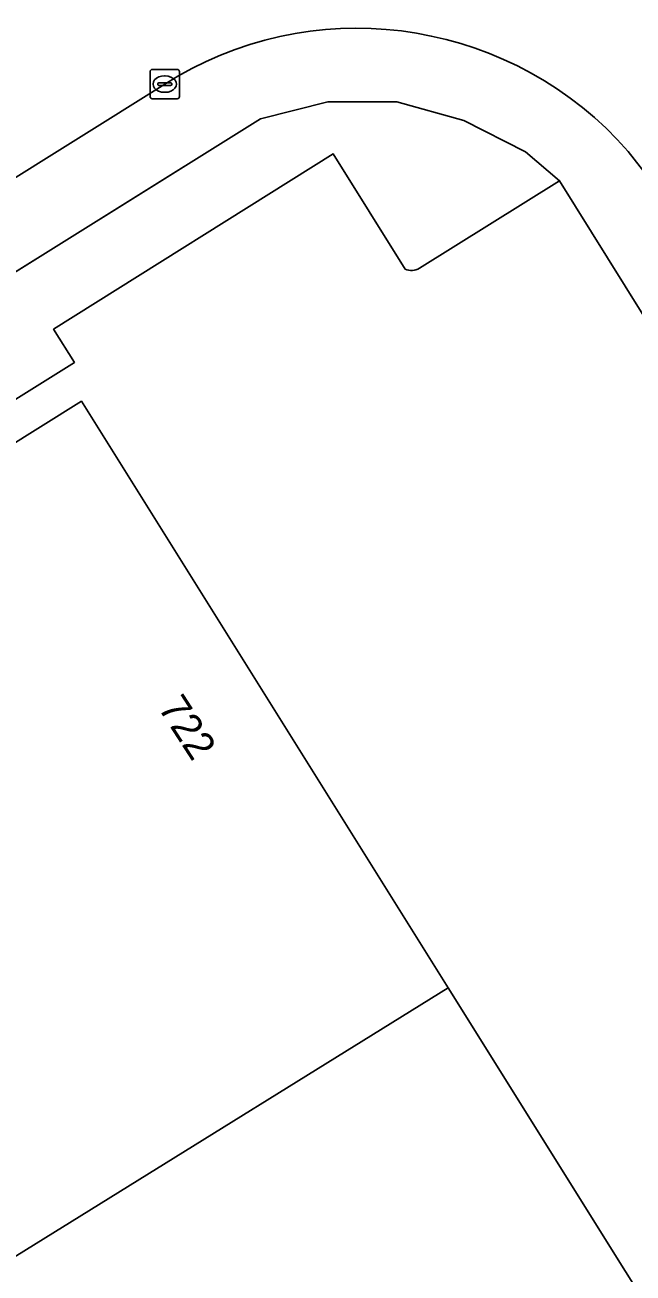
# Model space of a CAD drawing. Extents: x 158835 to 160077, y 386387 to 387778.
# Drawn here: x 159163.83 to 159184.56, y 386771.5 to 386814.08 of the extents above; entities that cross this region are included whole.
import ezdxf

# ---------------------------------------------------------------- set-up
doc = ezdxf.new("R2010")
doc.units = 0
for name, color, linetype in [('IMGEO_Groenvoorziening', 7, 'Continuous'), ('IMGEO_Hek', 7, 'Continuous'), ('IMGEO_Kolk', 7, 'Continuous'), ('IMGEO_Pand', 7, 'Continuous'), ('IMGEO_Pand_nummerreeks', 7, 'Continuous'), ('IMGEO_Parkeervlak_open', 7, 'Continuous'), ('IMGEO_Rijbaan_lokaal_open', 7, 'Continuous'), ('IMGEO_Voetpad_open', 7, 'Continuous')]:
    doc.layers.add(name, color=color, linetype=linetype)

msp = doc.modelspace()

# ---------------------------------------------------------------- linework, layer by layer
at = {"layer": 'IMGEO_Groenvoorziening'}
for points in [[(159177.277, 386805.78), (159182.052, 386808.764), (159180.897, 386809.75), (159178.798, 386810.825), (159176.512, 386811.455), (159174.154, 386811.455), (159171.857, 386810.878), (159139.124, 386790.423), (159139.345, 386790.071), (159136.479, 386788.27), (159138.209, 386785.502), (159141.086, 386787.3), (159165.512, 386802.566)], [(159165.512, 386802.566), (159164.804, 386803.7), (159174.335, 386809.688), (159176.795, 386805.752)]]:
    msp.add_lwpolyline(points, dxfattribs=at)
msp.add_arc((159177.009, 386806.225), 0.52, 245.6434, 301.0058, dxfattribs=at)
at = {"layer": 'IMGEO_Hek'}
msp.add_lwpolyline([(159189.265, 386797.201), (159182.052, 386808.764), (159180.897, 386809.75), (159178.798, 386810.825), (159176.512, 386811.455), (159174.154, 386811.455), (159171.857, 386810.878), (159136.254, 386788.629)], dxfattribs=at)
at = {"layer": 'IMGEO_Kolk'}
for p, q in [((159168.094, 386811.637), (159168.094, 386812.489)), ((159168.169, 386812.563), (159169.021, 386812.563)), ((159168.582, 386812.343), (159168.607, 386812.343)), ((159169.095, 386812.489), (159169.095, 386811.637)), ((159168.353, 386812.057), (159168.353, 386812.069)), ((159168.791, 386812.02), (159168.393, 386812.02)), ((159168.396, 386812.106), (159168.794, 386812.106)), ((159168.837, 386812.069), (159168.837, 386812.057)), ((159169.021, 386811.563), (159168.169, 386811.563)), ((159168.605, 386811.783), (159168.58, 386811.783))]:
    msp.add_line(p, q, dxfattribs=at)
for points in [[(159168.094, 386811.637), (159168.094, 386812.489)], [(159168.169, 386812.563), (159169.021, 386812.563)], [(159169.095, 386812.489), (159169.095, 386811.637)], [(159169.021, 386811.563), (159168.169, 386811.563)]]:
    msp.add_lwpolyline(points, dxfattribs=at)
for centre, radius, start, end in [((159168.171, 386812.487), 0.0765, 91.552, 178.448), ((159168.171, 386812.487), 0.0765, 91.552, 178.448), ((159169.019, 386812.487), 0.0765, 1.552, 88.448), ((159169.019, 386812.487), 0.0765, 1.552, 88.448), ((159168.393, 386812.066), 0.0403, 85.8775, 175.7526), ((159168.39, 386812.056), 0.0366, 178.938, 274.7102), ((159168.794, 386812.063), 0.043, 264.8664, 352.4533), ((159168.798, 386812.068), 0.0386, 1.7309, 96.639), ((159168.171, 386811.639), 0.0765, 181.552, 268.448), ((159168.171, 386811.639), 0.0765, 181.552, 268.448), ((159169.019, 386811.639), 0.0765, 271.552, 358.448), ((159169.019, 386811.639), 0.0765, 271.552, 358.448)]:
    msp.add_arc(centre, radius, start, end, dxfattribs=at)
for centre, major_axis, ratio, start_param, end_param in [((159168.581, 386812.063), (-0.387, 0.002), 0.722429, 4.712389, 7.853982), ((159168.606, 386812.063), (-0.39, 0.002), 0.717154, 1.570796, 4.712389)]:
    msp.add_ellipse(centre, major_axis=major_axis, ratio=ratio, start_param=start_param, end_param=end_param, dxfattribs=at)
at = {"layer": 'IMGEO_Pand'}
for points in [[(159151.946, 386764.896), (159178.263, 386781.231), (159165.755, 386801.244), (159148.655, 386790.54), (159148.938, 386790.077), (159142.585, 386786.136), (159144.171, 386783.519), (159141.399, 386781.766)], [(159190.357, 386761.88), (159178.263, 386781.231), (159151.946, 386764.896), (159165.863, 386742.636), (159169.168, 386744.695), (159170.897, 386741.999), (159172.84, 386743.213), (159173.128, 386742.771), (159194.106, 386755.882)]]:
    msp.add_lwpolyline(points, close=True, dxfattribs=at)
at = {"layer": 'IMGEO_Parkeervlak_open'}
for points in [[(159176.795, 386805.752), (159174.335, 386809.688), (159164.804, 386803.7), (159165.512, 386802.566), (159141.086, 386787.3)], [(159197.421, 386784.127), (159189.265, 386797.201), (159182.052, 386808.764), (159177.277, 386805.78)], [(159141.399, 386781.766), (159139.508, 386784.794), (159148.655, 386790.54), (159165.755, 386801.244), (159178.263, 386781.231), (159190.357, 386761.88), (159190.757, 386762.129), (159193.119, 386758.35), (159197.578, 386761.137), (159197.962, 386760.524)]]:
    msp.add_lwpolyline(points, dxfattribs=at)
msp.add_arc((159177.009, 386806.225), 0.52, 245.6434, 301.0058, dxfattribs=at)
at = {"layer": 'IMGEO_Rijbaan_lokaal_open'}
for points in [[(159184.396, 386809.768), (159185.669, 386808.14), (159186.192, 386807.255), (159191.052, 386799.421), (159194.344, 386794.115), (159194.994, 386793.062), (159200.369, 386784.406), (159210.158, 386768.643), (159210.42, 386768.242), (159215.915, 386771.769), (159215.795, 386771.927), (159215.274, 386772.727), (159214.927, 386773.26), (159203.911, 386791.078), (159196.853, 386802.486), (159190.237, 386813.13), (159189.98, 386813.56), (159188.119, 386816.595)], [(159138.697, 386793.358), (159138.936, 386793.516), (159153.686, 386802.738), (159168.594, 386812.064), (159169.036, 386812.337)]]:
    msp.add_lwpolyline(points, dxfattribs=at)
msp.add_arc((159175.151, 386801.696), 12.273, 41.1258, 119.8842, dxfattribs=at)
at = {"layer": 'IMGEO_Voetpad_open'}
for points in [[(159169.036, 386812.337), (159168.594, 386812.064), (159153.686, 386802.738), (159138.936, 386793.516), (159138.697, 386793.358)], [(159171.857, 386810.878), (159174.154, 386811.455), (159176.512, 386811.455), (159178.798, 386810.825), (159180.897, 386809.75), (159182.052, 386808.764), (159189.265, 386797.201), (159191.052, 386799.421), (159186.192, 386807.255), (159185.669, 386808.14), (159184.396, 386809.768)], [(159134.523, 386791.444), (159136.254, 386788.629), (159139.124, 386790.423), (159171.857, 386810.878)]]:
    msp.add_lwpolyline(points, dxfattribs=at)
msp.add_arc((159175.151, 386801.696), 12.273, 41.1258, 119.8842, dxfattribs=at)

# ---------------------------------------------------------------- texts
at = {"layer": 'IMGEO_Pand_nummerreeks'}
msp.add_text('722', height=1, rotation=302.8687, dxfattribs=at).set_placement((159168.345, 386790.793))

doc.saveas('drawing.dxf')
